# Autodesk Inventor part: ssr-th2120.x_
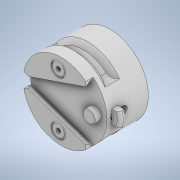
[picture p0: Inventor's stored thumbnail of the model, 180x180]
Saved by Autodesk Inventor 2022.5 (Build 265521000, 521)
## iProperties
Created: 2022-03
Part Number: ssr-th2120.x_
Material: 一般
Document SubType Name: Modeling
Designer: ImaoCorp
Density: 1 g/cm^3
Appearance: 既定
Sending System: SOLIDWORKS 2020-2020296
MC: AMD64
MC_MODEL: Intel64 Family 6 Model 60 Stepping 3, GenuineIntel
OS: Windows_NT
FRU: Parasolid Version 31.1, build 290,  3- 9-2020
FORMAT: text
GUISE: transmit
KEY: ssr-th2120 - Ql
FILE: ssr-th2120 - Ql.x_t
DATE: Tue Mar  8 13:30:06 2022
Author: ImaoCorp
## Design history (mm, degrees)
feature "Base1"
node "ソリッド1"
